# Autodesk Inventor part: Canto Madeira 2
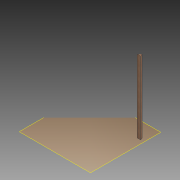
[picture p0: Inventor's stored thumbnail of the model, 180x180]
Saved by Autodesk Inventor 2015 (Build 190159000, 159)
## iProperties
Created: 2015-04
Part Number: Canto Madeira 2
Material: Wood (Birch)
Document SubType Name: Modeling
Designer: suporte
Density: 0.55 g/cm^3
Appearance: Birch - Natural Polished
Author: suporte
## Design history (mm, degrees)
workplane "Work Plane1"
sketch "Sketch1"
  geometry: L1 (572.263, 900)-(912.5, 560) reference; L2 (912.5, -900)-(912.5, 900) reference; L3 (812.5, 518.558)-(883.186, 589.294); L4 (912.5, 518.558)-(883.186, 589.294); L5 (912.5, 518.558)-(812.5, 518.558); 1 further point
  constraints: 6 end point, 2 perpendicular, 2 point on line, 1 other
extrude "Extrusion1" new body sketch "Sketch1" distance "d0" = 2050; taper "d1" = 0 deg
node "Direct Edit1"
node "Direct Edit2"
body "Solid1"
node "Reference1"
node "Reference2"
feature "Size1" dims "d2" = -1
feature "Size2" dims "d3" = -1
